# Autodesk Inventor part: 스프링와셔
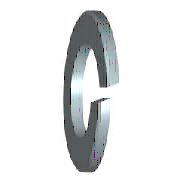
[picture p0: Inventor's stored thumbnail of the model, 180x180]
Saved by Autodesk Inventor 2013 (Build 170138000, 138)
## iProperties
Created: 2012-02
Part Number: 스프링와셔
Material: 강철, 연강
Description: 스프링 와셔
Document SubType Name: Modeling
Standard: JIS B 1251
Designer: mduedu
Standards Organization: JIS
Language: ko-KR
Size Designation: 번호 2 4
Categories: <MemberInstance><Categories><Category DisplayName="조임쇠" InternalName="e4da775c-781d-43d5-af7c-5136215cf5a6" Mnemonic="FSTN"><Category DisplayName="와셔" InternalN
Density: 1 g/cm^3
IsCustomPart: 1
Author: mduedu
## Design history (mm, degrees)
sketch "스케치1"
  geometry: C1 r 3.8 at (0, 0); C2 r 2.05 at (0, 0); 1 further point
  constraints: 2 centre point, 2 coincident
  dimensions: "d0" = 4.1 diameter of C2 (= SD1); "d1" = 7.6 diameter of C1 (= SD2)
extrude "본체" new body sketch "스케치1" distance "d2" = 1 (= SD); taper "d3" = 0 deg
sketch "스케치2"
  geometry: L1 (0, -2.05)-(0, 2.05) reference; L2 (1, 3.8)-(1, -3.8) reference; L3 (-1.2, 0)-(7.2, 0) reference; L4 (0, -0.2)-(1, 0.164); L5 (0, 0.2)-(1, 0.564)
  constraints: 4 end point, 4 point on line, 1 parallel
  dimensions: "d4" = 0.2 distance from line of L3 L4.start (= 0.2 x SD); "d5" = 0.2 distance from line of L3 L5.start (= 0.2 x SD); "d6" = 70 deg angle of L2 L4 (= FAWI)
extrude "절단부" cut sketch "스케치2" stored distance "d7" = 1 (= SD); taper "d8" = 0 deg
workaxis "Work Axis1"
workplane "Work Plane1"
body "Solid1"
other parameters: "SD1" = 4.1 [user parameter; used in 1 equation term], "SD2" = 7.6 [user parameter; used in 1 equation term], "SD" = 1 [user parameter; used in 4 equation terms], "FAWI" = 70 deg [user parameter; used in 1 equation term], "d9" = 0, "d10" = 0, "d11" = 0, "d12" = 0, "SDI" = 1.4 [user parameter], "NND" = 4 [user parameter]
